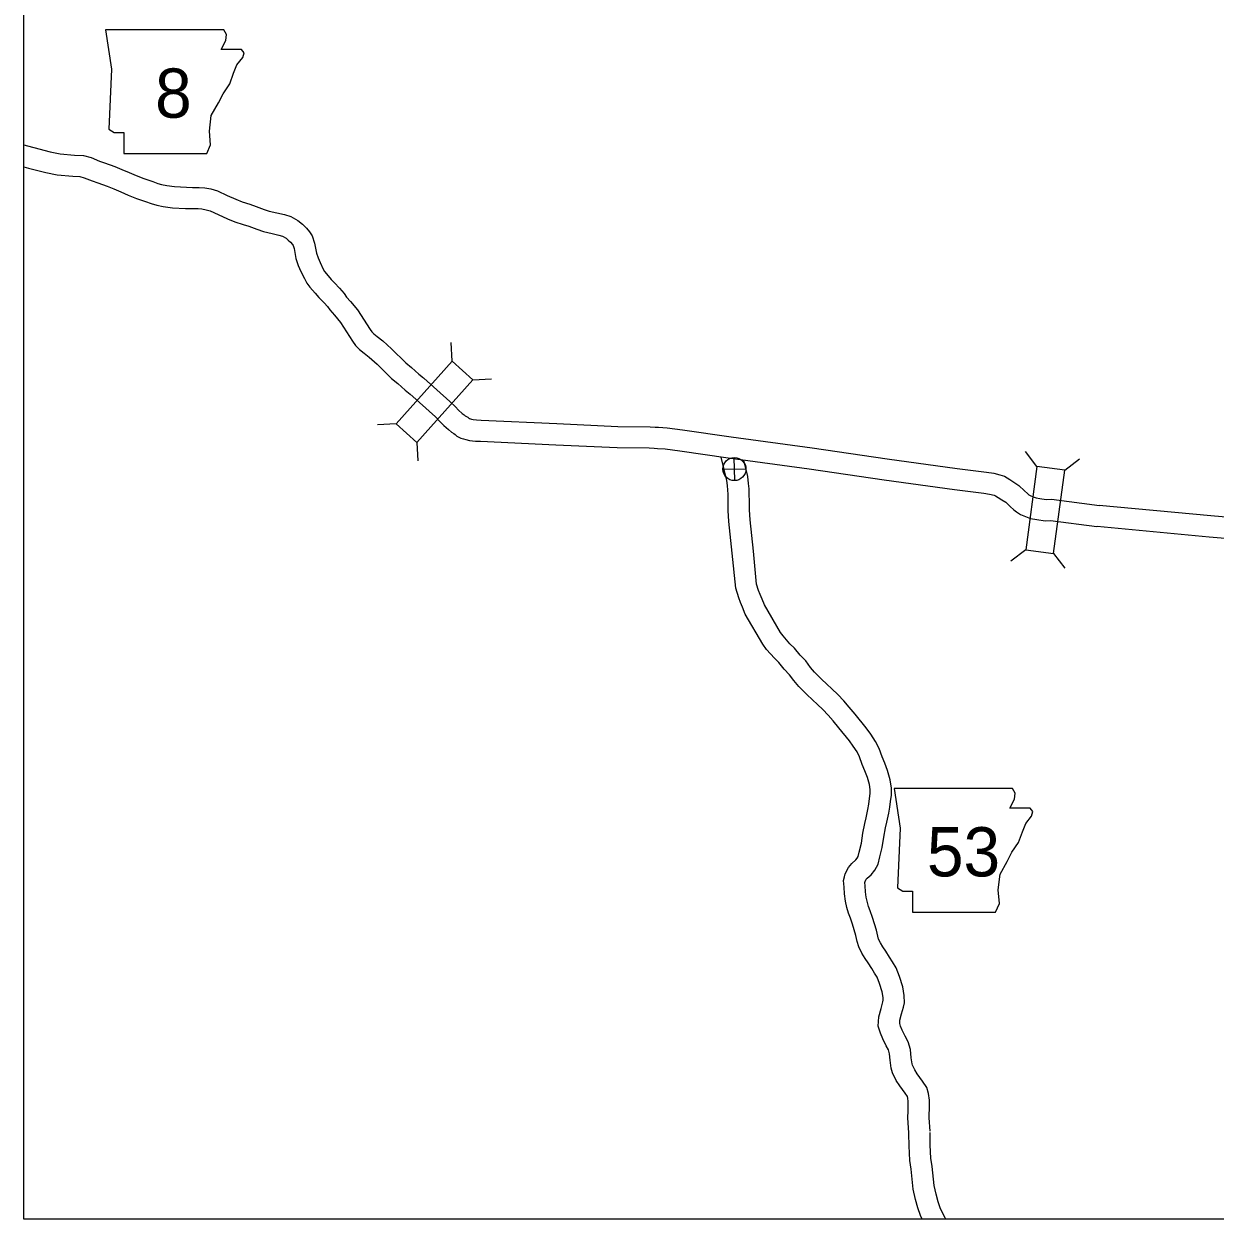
# Model space of a CAD drawing. Extents: x 1373862 to 1377080, y 1164775 to 1170415.
# Drawn here: x 1373884.5 to 1374053.1, y 1169861.9 to 1170031.1 of the extents above; entities that cross this region are included whole.
import ezdxf

# ---------------------------------------------------------------- set-up
doc = ezdxf.new("R2010")
doc.units = 0
doc.layers.add('1', color=7, linetype='Continuous')
doc.layers.add('Default', color=7, linetype='Continuous')

msp = doc.modelspace()

# ---------------------------------------------------------------- linework, layer by layer
at = {"layer": '1'}
msp.add_lwpolyline([(1373884.49, 1170388.77), (1374613.88, 1170388.77), (1374613.88, 1169861.94), (1373884.49, 1169861.94)], close=True, dxfattribs=at)
at = {"layer": 'Default'}
for p, q in [((1373945.1, 1169983.38), (1373944.96, 1169986.01)), ((1373948.05, 1169980.73), (1373950.69, 1169980.87)), ((1373937.17, 1169974.53), (1373934.53, 1169974.39)), ((1373940.12, 1169971.89), (1373940.26, 1169969.25)), ((1373985.12, 1169966.48), (1373985.04, 1169969.73)), ((1374027.91, 1169968.47), (1374026.31, 1169970.57)), ((1374031.84, 1169967.94), (1374033.94, 1169969.54)), ((1373983.45, 1169968.07), (1373986.71, 1169968.14)), ((1374026.32, 1169956.69), (1374024.22, 1169955.09)), ((1374030.25, 1169956.16), (1374031.85, 1169954.06))]:
    msp.add_line(p, q, dxfattribs=at)
for points in [[(1373896.04, 1170030.27), (1373896.87, 1170024.69), (1373896.5, 1170016.22), (1373897.25, 1170015.75), (1373898.64, 1170015.75), (1373898.64, 1170012.78), (1373910.37, 1170012.78), (1373910.92, 1170013.99), (1373910.74, 1170015.94), (1373911.02, 1170018.17), (1373912.04, 1170019.94), (1373912.69, 1170021.24), (1373913.62, 1170022.64), (1373914.18, 1170024.13), (1373914.65, 1170025.34), (1373915.48, 1170026.36), (1373915.67, 1170027.01), (1373915.3, 1170027.48), (1373912.41, 1170027.48), (1373913.07, 1170028.78), (1373913.16, 1170029.62), (1373912.77, 1170030.26)], [(1373945.1, 1169983.38), (1373937.17, 1169974.53), (1373940.12, 1169971.89), (1373948.05, 1169980.73)], [(1374030.25, 1169956.16), (1374031.84, 1169967.94), (1374027.91, 1169968.47), (1374026.32, 1169956.69)], [(1374007.71, 1169922.89), (1374008.54, 1169917.3), (1374008.17, 1169908.84), (1374008.92, 1169908.37), (1374010.31, 1169908.37), (1374010.31, 1169905.39), (1374022.03, 1169905.39), (1374022.59, 1169906.6), (1374022.41, 1169908.56), (1374022.69, 1169910.79), (1374023.71, 1169912.56), (1374024.36, 1169913.86), (1374025.29, 1169915.26), (1374025.85, 1169916.75), (1374026.32, 1169917.96), (1374027.15, 1169918.98), (1374027.34, 1169919.63), (1374026.97, 1169920.1), (1374024.08, 1169920.1), (1374024.73, 1169921.4), (1374024.83, 1169922.24), (1374024.44, 1169922.88)]]:
    msp.add_lwpolyline(points, close=True, dxfattribs=at)
for points in [[(1373884.49, 1170014), (1373884.99, 1170013.85), (1373885.9, 1170013.6), (1373888.22, 1170013.01), (1373889.63, 1170012.74), (1373891.66, 1170012.55), (1373892.9, 1170012.48), (1373893.99, 1170012.19), (1373895.17, 1170011.71), (1373895.91, 1170011.46), (1373897.36, 1170010.95), (1373898.37, 1170010.52), (1373899.4, 1170010.08), (1373900.38, 1170009.65), (1373901.47, 1170009.23), (1373902.73, 1170008.8), (1373903.43, 1170008.54), (1373903.98, 1170008.39), (1373904.71, 1170008.25), (1373905.83, 1170008.08), (1373907.5, 1170007.99), (1373908.35, 1170007.97), (1373909.31, 1170007.97), (1373910.1, 1170007.9), (1373910.94, 1170007.75), (1373911.9, 1170007.49), (1373913.24, 1170006.85), (1373914.49, 1170006.3), (1373915.37, 1170005.94), (1373916.47, 1170005.59), (1373917.37, 1170005.29), (1373918.48, 1170004.86), (1373919.22, 1170004.61), (1373920.28, 1170004.38), (1373921.36, 1170004.12), (1373922.29, 1170003.84), (1373923.28, 1170003.3), (1373923.92, 1170002.77), (1373924.51, 1170002.2), (1373924.9, 1170001.68), (1373925.32, 1170001.1), (1373925.64, 1170000.08), (1373925.91, 1169998.68), (1373926.13, 1169998.01), (1373926.43, 1169997.36), (1373926.87, 1169996.42), (1373927.06, 1169996.08), (1373927.31, 1169995.76), (1373927.98, 1169994.96), (1373928.45, 1169994.45), (1373929.19, 1169993.69), (1373929.85, 1169992.94), (1373930.17, 1169992.46), (1373930.71, 1169991.83), (1373931.72, 1169990.65), (1373933.5, 1169987.88), (1373933.75, 1169987.52), (1373934.01, 1169987.26), (1373934.49, 1169986.88), (1373935.31, 1169986.26), (1373936.54, 1169985.14), (1373938.56, 1169983.16), (1373939.37, 1169982.48), (1373940.42, 1169981.56), (1373941.07, 1169981.03)], [(1373884.49, 1170010.88), (1373885.14, 1170010.7), (1373887.57, 1170010.08), (1373889.21, 1170009.77), (1373891.43, 1170009.56), (1373892.42, 1170009.5), (1373893.03, 1170009.34), (1373894.13, 1170008.89), (1373894.94, 1170008.62), (1373896.27, 1170008.15), (1373897.2, 1170007.75), (1373898.21, 1170007.33), (1373899.24, 1170006.88), (1373900.45, 1170006.41), (1373901.72, 1170005.97), (1373902.5, 1170005.68), (1373903.31, 1170005.46), (1373904.21, 1170005.29), (1373905.52, 1170005.1), (1373907.38, 1170004.99), (1373908.32, 1170004.97), (1373909.18, 1170004.97), (1373909.7, 1170004.93), (1373910.28, 1170004.82), (1373910.85, 1170004.67), (1373911.99, 1170004.12), (1373913.32, 1170003.54), (1373914.33, 1170003.12), (1373915.54, 1170002.73), (1373916.35, 1170002.47), (1373917.45, 1170002.04), (1373918.42, 1170001.71), (1373919.62, 1170001.45), (1373920.57, 1170001.23), (1373921.12, 1170001.06), (1373921.6, 1170000.8), (1373921.92, 1170000.53), (1373922.25, 1170000.21), (1373922.49, 1169999.9), (1373922.6, 1169999.75), (1373922.73, 1169999.34), (1373923, 1169997.93), (1373923.33, 1169996.91), (1373923.71, 1169996.09), (1373924.2, 1169995.06), (1373924.56, 1169994.41), (1373924.99, 1169993.86), (1373925.72, 1169992.99), (1373926.26, 1169992.39), (1373926.99, 1169991.65), (1373927.47, 1169991.11), (1373927.78, 1169990.64), (1373928.44, 1169989.87), (1373929.31, 1169988.85), (1373931.01, 1169986.22), (1373931.43, 1169985.61), (1373932, 1169985.02), (1373932.66, 1169984.5), (1373933.39, 1169983.95), (1373934.48, 1169982.96), (1373936.55, 1169980.93), (1373937.42, 1169980.21), (1373938.47, 1169979.27), (1373939.18, 1169978.7)], [(1373941.12, 1169980.98), (1373944.81, 1169977.67), (1373945.57, 1169976.9), (1373946.02, 1169976.43), (1373946.52, 1169975.99), (1373946.81, 1169975.76), (1373946.97, 1169975.66), (1373947.33, 1169975.44), (1373947.52, 1169975.27), (1373947.57, 1169975.25), (1373947.85, 1169975.17), (1373948.08, 1169975.11), (1373948.58, 1169975.06), (1373949.23, 1169975.05), (1373959.95, 1169974.54), (1373968.58, 1169974.14), (1373973.14, 1169974.1), (1373973.85, 1169974.06), (1373974.32, 1169974.04), (1373975.56, 1169973.95), (1373977.75, 1169973.67), (1373984.62, 1169972.68), (1373996.09, 1169971.09), (1374006.7, 1169969.56), (1374016.61, 1169968.17), (1374020.78, 1169967.68), (1374021.82, 1169967.51), (1374022.67, 1169967.29), (1374023.31, 1169967.08), (1374024.08, 1169966.62), (1374024.62, 1169966.24), (1374025.34, 1169965.78), (1374026.16, 1169965.02), (1374026.59, 1169964.63), (1374026.78, 1169964.47), (1374026.97, 1169964.35), (1374027.39, 1169964.17), (1374027.78, 1169964.03), (1374028.34, 1169963.93), (1374029.23, 1169963.81), (1374029.99, 1169963.83), (1374036.77, 1169962.95)], [(1373939.12, 1169978.75), (1373942.74, 1169975.5), (1373943.42, 1169974.81), (1373943.94, 1169974.27), (1373944.59, 1169973.7), (1373945.04, 1169973.34), (1373945.37, 1169973.12), (1373945.54, 1169973.01), (1373945.8, 1169972.78), (1373946.36, 1169972.48), (1373946.71, 1169972.38), (1373947.05, 1169972.28), (1373947.56, 1169972.15), (1373948.41, 1169972.06), (1373949.14, 1169972.06), (1373959.81, 1169971.54), (1373968.5, 1169971.14), (1373973.02, 1169971.1), (1373973.7, 1169971.06), (1373974.17, 1169971.04), (1373975.27, 1169970.97), (1373977.34, 1169970.7), (1373984.2, 1169969.71), (1373995.67, 1169968.12), (1374006.28, 1169966.59), (1374016.23, 1169965.2), (1374020.37, 1169964.7), (1374021.21, 1169964.57), (1374021.83, 1169964.41), (1374022.05, 1169964.34), (1374022.44, 1169964.1), (1374022.95, 1169963.75), (1374023.5, 1169963.4), (1374024.13, 1169962.82), (1374024.62, 1169962.36), (1374025.02, 1169962.03), (1374025.57, 1169961.69), (1374026.3, 1169961.37), (1374027.01, 1169961.12), (1374027.88, 1169960.96), (1374029.08, 1169960.8), (1374029.84, 1169960.82), (1374036.38, 1169959.97)], [(1374009.79, 1169874.16), (1374009.63, 1169876.26), (1374009.68, 1169877.26), (1374009.7, 1169877.43), (1374009.69, 1169878.1), (1374009.7, 1169878.6), (1374009.64, 1169879.05), (1374009.56, 1169879.28), (1374009.26, 1169879.75), (1374008.49, 1169880.8), (1374007.97, 1169881.58), (1374007.46, 1169882.67), (1374007.27, 1169883.32), (1374007.14, 1169884.43), (1374007.04, 1169885.33), (1374006.87, 1169885.91), (1374006.57, 1169886.48), (1374006.07, 1169887.46), (1374005.76, 1169888.28), (1374005.45, 1169889.24), (1374005.54, 1169890.56), (1374005.84, 1169891.74), (1374006.09, 1169892.7), (1374006.14, 1169892.91), (1374006.13, 1169893.29), (1374005.99, 1169894.1), (1374005.63, 1169895.3), (1374005.3, 1169896.17), (1374004.92, 1169896.77), (1374004.51, 1169897.43), (1374004, 1169898.24), (1374003.59, 1169898.85), (1374003.14, 1169899.57), (1374002.68, 1169900.48), (1374002.45, 1169901.26), (1374002.26, 1169902.1), (1374001.8, 1169903.71), (1374001.49, 1169904.53), (1374001.22, 1169905.26), (1374001, 1169906.03), (1374000.8, 1169906.96), (1374000.65, 1169907.96), (1374000.6, 1169908.93), (1374000.57, 1169909.39), (1374000.53, 1169909.89), (1374000.67, 1169910.41), (1374000.77, 1169910.83), (1374001.24, 1169911.7), (1374001.72, 1169912.3), (1374002.29, 1169912.78), (1374002.47, 1169913.02), (1374002.61, 1169913.26), (1374002.74, 1169913.88), (1374003.05, 1169915.15), (1374003.28, 1169916.55), (1374003.55, 1169917.95), (1374003.73, 1169918.76), (1374003.97, 1169919.93), (1374004.09, 1169920.69), (1374004.21, 1169921.47), (1374004.31, 1169922.17), (1374004.32, 1169922.74), (1374004.21, 1169923.46), (1374003.9, 1169924.46), (1374003.55, 1169925.4), (1374003.18, 1169926.31), (1374002.79, 1169927.37), (1374002.44, 1169928.06), (1374001.91, 1169928.88), (1374001.35, 1169929.66), (1373999.86, 1169931.49), (1373999.04, 1169932.46), (1373998.33, 1169933.29), (1373997.59, 1169934.09), (1373996.84, 1169934.79), (1373996.11, 1169935.46), (1373995.31, 1169936.22), (1373994.2, 1169937.34), (1373993.51, 1169938.16), (1373992.88, 1169939), (1373992.14, 1169939.78), (1373991.36, 1169940.71), (1373990.73, 1169941.34), (1373989.64, 1169942.59), (1373989.1, 1169943.3), (1373986.61, 1169947.57), (1373986.23, 1169948.56), (1373985.96, 1169949.22), (1373985.68, 1169949.9), (1373985.26, 1169951.24), (1373984.78, 1169956.18), (1373984.31, 1169960.69), (1373984.21, 1169962.24), (1373984.2, 1169963.38), (1373984.18, 1169964.54), (1373984.15, 1169965.12), (1373984.1, 1169965.77), (1373984.02, 1169966.51), (1373983.2, 1169969.81)], [(1374012.78, 1169874.39), (1374012.64, 1169876.3), (1374012.67, 1169877.04), (1374012.7, 1169877.29), (1374012.69, 1169878.07), (1374012.71, 1169878.78), (1374012.57, 1169879.73), (1374012.3, 1169880.59), (1374011.72, 1169881.47), (1374010.95, 1169882.51), (1374010.6, 1169883.05), (1374010.27, 1169883.73), (1374010.22, 1169883.91), (1374010.12, 1169884.78), (1374010, 1169885.93), (1374009.66, 1169887.04), (1374009.24, 1169887.86), (1374008.82, 1169888.67), (1374008.6, 1169889.27), (1374008.48, 1169889.62), (1374008.51, 1169890.08), (1374008.75, 1169890.99), (1374009, 1169891.95), (1374009.15, 1169892.56), (1374009.13, 1169893.58), (1374008.91, 1169894.8), (1374008.47, 1169896.27), (1374008, 1169897.51), (1374007.47, 1169898.36), (1374007.05, 1169899.02), (1374006.52, 1169899.88), (1374006.11, 1169900.48), (1374005.76, 1169901.04), (1374005.48, 1169901.59), (1374005.36, 1169902.01), (1374005.17, 1169902.85), (1374004.65, 1169904.64), (1374004.31, 1169905.57), (1374004.07, 1169906.2), (1374003.91, 1169906.77), (1374003.75, 1169907.5), (1374003.64, 1169908.25), (1374003.6, 1169909.11), (1374003.56, 1169909.6), (1374003.56, 1169909.62), (1374003.57, 1169909.67), (1374003.59, 1169909.73), (1374003.75, 1169910.04), (1374003.88, 1169910.2), (1374004.46, 1169910.69), (1374004.98, 1169911.35), (1374005.45, 1169912.19), (1374005.67, 1169913.22), (1374005.99, 1169914.56), (1374006.24, 1169916.02), (1374006.49, 1169917.34), (1374006.67, 1169918.13), (1374006.92, 1169919.39), (1374007.06, 1169920.23), (1374007.18, 1169921.03), (1374007.31, 1169921.93), (1374007.32, 1169922.94), (1374007.14, 1169924.13), (1374006.74, 1169925.42), (1374006.35, 1169926.49), (1374005.98, 1169927.39), (1374005.55, 1169928.56), (1374005.05, 1169929.56), (1374004.38, 1169930.58), (1374003.74, 1169931.47), (1374002.17, 1169933.41), (1374001.32, 1169934.41), (1374000.57, 1169935.28), (1373999.72, 1169936.21), (1373998.88, 1169936.99), (1373998.16, 1169937.65), (1373997.4, 1169938.37), (1373996.42, 1169939.36), (1373995.86, 1169940.03), (1373995.17, 1169940.94), (1373994.39, 1169941.77), (1373993.57, 1169942.74), (1373992.92, 1169943.39), (1373991.97, 1169944.48), (1373991.59, 1169944.98), (1373989.33, 1169948.87), (1373989.02, 1169949.67), (1373988.73, 1169950.37), (1373988.5, 1169950.92), (1373988.22, 1169951.83), (1373987.77, 1169956.48), (1373987.3, 1169960.94), (1373987.21, 1169962.35), (1373987.2, 1169963.42), (1373987.18, 1169964.65), (1373987.15, 1169965.31), (1373987.09, 1169966.06), (1373986.97, 1169967.05), (1373986.4, 1169969.37)], [(1374056.25, 1169961.17), (1374052.55, 1169961.48), (1374036.71, 1169962.95)], [(1374056.23, 1169958.16), (1374052.28, 1169958.49), (1374036.43, 1169959.97)], [(1374011.65, 1169861.94), (1374011.43, 1169862.43), (1374011.06, 1169863.52), (1374010.71, 1169864.74), (1374010.39, 1169866.19), (1374010.08, 1169869), (1374009.89, 1169870.25), (1374009.8, 1169872.32), (1374009.77, 1169874.02), (1374009.79, 1169874.34)], [(1374015, 1169861.94), (1374014.91, 1169862.11), (1374014.55, 1169862.83), (1374014.21, 1169863.55), (1374013.92, 1169864.4), (1374013.63, 1169865.47), (1374013.36, 1169866.69), (1374013.06, 1169869.39), (1374012.88, 1169870.55), (1374012.8, 1169872.41), (1374012.77, 1169873.97), (1374012.79, 1169874.21)]]:
    msp.add_lwpolyline(points, dxfattribs=at)
msp.add_circle((1373985.08, 1169968.1), 1.63, dxfattribs=at)

# ---------------------------------------------------------------- texts
for s, p in [('8', (1373903.06, 1170017.84)), ('53', (1374012.33, 1169910.45))]:
    msp.add_text(s, height=6.97, dxfattribs=at).set_placement(p)

doc.saveas('drawing.dxf')
